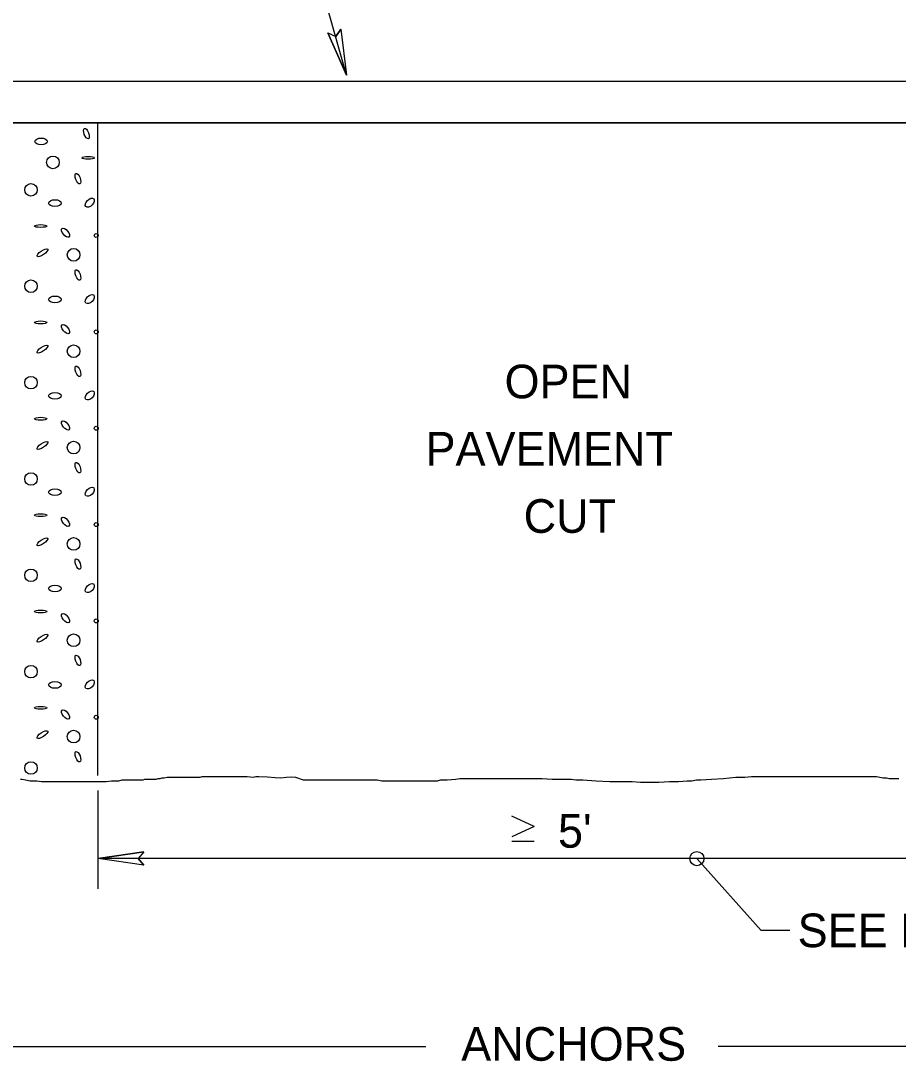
# Model space of a CAD drawing. Extents: x 12.5 to 19.6, y 6 to 16.
# Drawn here: x 14.897 to 16.462, y 11.205 to 13.061 of the extents above; entities that cross this region are included whole.
import ezdxf

# ---------------------------------------------------------------- set-up
doc = ezdxf.new("R2010")
doc.units = 0
for name, color, linetype in [('DETL-DIMS', 7, 'Continuous'), ('DETL-NOTE', 7, 'Continuous'), ('PVMT-FILL', 7, 'Continuous'), ('ROAD-EDGE', 7, 'Continuous'), ('SECT-SUBP_P', 7, 'Continuous')]:
    doc.layers.add(name, color=color, linetype=linetype)

msp = doc.modelspace()

# ---------------------------------------------------------------- linework, layer by layer
at = {"layer": 'DETL-DIMS'}
for p, q in [((15.4444, 13.0396), (15.4782, 12.964)), ((15.4444, 13.0396), (15.4587, 13.033)), ((15.4675, 13.0461), (15.4587, 13.033)), ((15.4675, 13.0461), (15.4782, 12.964)), ((15.1166, 11.5784), (15.0348, 11.5665)), ((16.7348, 11.5665), (15.0348, 11.5665)), ((15.1166, 11.5546), (15.0348, 11.5665)), ((15.1166, 11.5784), (15.1065, 11.5665)), ((15.1166, 11.5546), (15.1065, 11.5665)), ((16.2179, 11.4379), (16.103, 11.5664)), ((16.2687, 11.4379), (16.2179, 11.4379))]:
    msp.add_line(p, q, dxfattribs=at)
for points in [[(15.4782, 12.964), (15.3133, 13.5481), (15.5331, 13.5481)], [(17.2355, 12.5529), (17.6317, 11.2314), (16.1411, 11.2314)], [(14.5403, 12.5179), (14.1363, 11.2314), (15.6196, 11.2314)]]:
    msp.add_lwpolyline(points, dxfattribs=at)
for points in [[(15.4675, 13.0461), (15.4782, 12.964), (15.4444, 13.0396), (15.4587, 13.033)], [(15.1166, 11.5546), (15.0348, 11.5665), (15.1166, 11.5784), (15.1065, 11.5665)]]:
    msp.add_lwpolyline(points, close=True, dxfattribs=at)
msp.add_circle((16.103, 11.5664), 0.0126, dxfattribs=at)
at = {"layer": 'DETL-NOTE'}
for p, q in [((15.8126, 11.6237), (15.7726, 11.6423)), ((15.8126, 11.6237), (15.7726, 11.6051)), ((15.7726, 11.5976), (15.8126, 11.5976))]:
    msp.add_line(p, q, dxfattribs=at)
at = {"layer": 'PVMT-FILL'}
for points in [[(15.3005, 11.7127), (15.3114, 11.712), (15.3164, 11.713), (15.3217, 11.7131), (15.3368, 11.7124), (15.3508, 11.7112), (15.361, 11.7107), (15.3708, 11.7118), (15.3806, 11.7125), (15.387, 11.7119), (15.4009, 11.7067), (15.4179, 11.7067), (15.4433, 11.7067), (15.4602, 11.7067), (15.4747, 11.7067), (15.4892, 11.7067), (15.4953, 11.7067), (15.5062, 11.7067), (15.5207, 11.7067), (15.5328, 11.7067), (15.5412, 11.7055), (15.5642, 11.7055), (15.5799, 11.7055), (15.5969, 11.7055), (15.6041, 11.7055), (15.6114, 11.7055), (15.6235, 11.7055), (15.632, 11.7055), (15.6356, 11.7055), (15.6404, 11.7055), (15.6453, 11.7067), (15.6574, 11.7067), (15.6731, 11.7079), (15.6803, 11.7091), (15.6852, 11.7091), (15.6912, 11.7091), (15.6985, 11.7091), (15.7118, 11.7091), (15.7166, 11.7091), (15.7251, 11.7091), (15.7396, 11.7091), (15.7469, 11.7091), (15.7638, 11.7091), (15.7735, 11.7091), (15.7844, 11.7091), (15.7916, 11.7091), (15.7965, 11.7091), (15.8001, 11.7091), (15.8049, 11.7091), (15.811, 11.7091), (15.8267, 11.7091), (15.8449, 11.7079), (15.8473, 11.7079), (15.8533, 11.7079), (15.8678, 11.7079), (15.8787, 11.7079), (15.8872, 11.7067), (15.8993, 11.7067), (15.9235, 11.7055), (15.9477, 11.7043), (15.9549, 11.7043), (15.9622, 11.7043), (15.9743, 11.7043), (15.9803, 11.7043), (15.9876, 11.7043), (16.0021, 11.7031), (16.0106, 11.7031), (16.0348, 11.7031), (16.0541, 11.7043), (16.0699, 11.7043), (16.0856, 11.7055), (16.094, 11.7055), (16.1025, 11.7067), (16.1098, 11.7067), (16.1291, 11.7079), (16.1497, 11.7091), (16.1727, 11.7115), (16.1884, 11.7115), (16.2005, 11.7127), (16.2053, 11.7127), (16.2126, 11.7127), (16.2199, 11.7127), (16.2259, 11.7127), (16.2307, 11.7127), (16.2428, 11.7127), (16.2513, 11.7127), (16.2646, 11.7127), (16.2719, 11.7127), (16.2779, 11.7127), (16.2828, 11.7127), (16.2949, 11.7127), (16.3069, 11.7127), (16.3142, 11.7127), (16.3275, 11.7127), (16.3384, 11.7127), (16.3493, 11.7127), (16.3541, 11.7127), (16.3602, 11.7127), (16.3686, 11.7127), (16.3819, 11.7127), (16.3928, 11.7127), (16.3989, 11.7127), (16.4122, 11.7127), (16.4231, 11.7127), (16.4352, 11.7103), (16.4412, 11.7103), (16.4461, 11.7091), (16.4509, 11.7091), (16.463, 11.7091)], [(14.8965, 11.7079), (14.8989, 11.7079), (14.905, 11.7067), (14.9134, 11.7055), (14.9255, 11.7055), (14.934, 11.7043), (14.9437, 11.7043), (14.9485, 11.7043), (14.9521, 11.7043), (14.957, 11.7043), (14.9618, 11.7043), (14.9667, 11.7043), (14.9727, 11.7043), (14.98, 11.7043), (14.9872, 11.7043), (14.9945, 11.7043), (15.0078, 11.7043), (15.015, 11.7043), (15.0211, 11.7043), (15.0235, 11.7043), (15.0259, 11.7043), (15.0283, 11.7043), (15.0344, 11.7043), (15.0441, 11.7043), (15.0489, 11.7043), (15.0586, 11.7055), (15.0634, 11.7055), (15.0671, 11.7055), (15.0683, 11.7055), (15.0695, 11.7055), (15.0707, 11.7055), (15.0719, 11.7055), (15.0779, 11.7067), (15.0804, 11.7067), (15.084, 11.7067), (15.0864, 11.7067), (15.09, 11.7067), (15.0912, 11.7067), (15.0925, 11.7067), (15.0937, 11.7067), (15.0949, 11.7067), (15.0973, 11.7067), (15.0985, 11.7067), (15.1009, 11.7067), (15.1021, 11.7067), (15.1046, 11.7067), (15.107, 11.7067), (15.1094, 11.7067), (15.1118, 11.7067), (15.113, 11.7067), (15.1154, 11.7067), (15.1179, 11.7079), (15.1263, 11.7079), (15.1287, 11.7079), (15.1324, 11.7079), (15.1372, 11.7079), (15.1384, 11.7079), (15.1421, 11.7091), (15.1457, 11.7091), (15.1493, 11.7103), (15.1529, 11.7103), (15.1578, 11.7115), (15.1675, 11.7115), (15.1771, 11.7115), (15.182, 11.7115), (15.1868, 11.7115), (15.1929, 11.7115), (15.1965, 11.7115), (15.2025, 11.7115), (15.211, 11.7115), (15.2171, 11.7115), (15.2207, 11.7127), (15.2267, 11.7127), (15.2316, 11.7127), (15.2376, 11.7127), (15.2388, 11.7127), (15.2412, 11.7127), (15.2461, 11.7127), (15.2509, 11.7127), (15.2606, 11.7127), (15.2666, 11.7127), (15.2703, 11.7127), (15.2727, 11.7127), (15.2739, 11.7127), (15.2775, 11.7127), (15.2787, 11.7127), (15.28, 11.7127), (15.2836, 11.7127), (15.2884, 11.7127), (15.2908, 11.7127), (15.2933, 11.7127), (15.2957, 11.7127), (15.2969, 11.7127), (15.2981, 11.7127), (15.2993, 11.7127), (15.3005, 11.7127)]]:
    msp.add_lwpolyline(points, dxfattribs=at)
for centre, radius in [((14.9542, 12.8086), 0.0112), ((14.915, 12.7596), 0.0112), ((15.0314, 12.6782), 0.00349), ((14.991, 12.6437), 0.0113), ((14.915, 12.5877), 0.0112), ((15.0314, 12.5062), 0.00349), ((14.991, 12.4718), 0.0113), ((14.915, 12.4157), 0.0112), ((15.0314, 12.3343), 0.00349), ((14.991, 12.2999), 0.0113), ((14.915, 12.2438), 0.0112), ((15.0314, 12.1624), 0.00349), ((14.991, 12.1279), 0.0113), ((14.915, 12.0719), 0.0112), ((15.0314, 11.9905), 0.00349), ((14.991, 11.956), 0.0113), ((14.915, 11.9), 0.0112), ((15.0314, 11.8186), 0.00349), ((14.991, 11.7841), 0.0113), ((14.915, 11.7281), 0.0112)]:
    msp.add_circle(centre, radius, dxfattribs=at)
for centre, major_axis, ratio in [((15.0139, 12.8601), (0.00349, -0.00926), 0.407015), ((14.9332, 12.846), (0.0112, 0), 0.539468), ((15.017, 12.8167), (0.0112, 0), 0.226521), ((14.9988, 12.7796), (0.00349, -0.00926), 0.407015), ((14.9578, 12.736), (0.0112, 0), 0.539468), ((15.02, 12.7367), (-0.007, -0.007), 0.581564), ((14.9323, 12.6951), (0.0112, 0), 0.226521), ((14.9766, 12.6832), (-0.00613, 0.00777), 0.467307), ((14.9355, 12.6473), (0.00937, 0.00627), 0.338582), ((14.9988, 12.6077), (0.00349, -0.00926), 0.407015), ((14.9578, 12.5641), (0.0112, 0), 0.539468), ((15.02, 12.5647), (-0.007, -0.007), 0.581564), ((14.9323, 12.5232), (0.0112, 0), 0.226521), ((14.9766, 12.5112), (-0.00613, 0.00777), 0.467307), ((14.9355, 12.4754), (0.00937, 0.00627), 0.338582), ((14.9988, 12.4358), (0.00349, -0.00926), 0.407015), ((15.02, 12.3928), (-0.007, -0.007), 0.581564), ((14.9578, 12.3922), (0.0112, 0), 0.539468), ((14.9323, 12.3513), (0.0112, 0), 0.226521), ((14.9766, 12.3393), (-0.00613, 0.00777), 0.467307), ((14.9355, 12.3035), (0.00937, 0.00627), 0.338582), ((14.9988, 12.2639), (0.00349, -0.00926), 0.407015), ((14.9578, 12.2202), (0.0112, 0), 0.539468), ((15.02, 12.2209), (-0.007, -0.007), 0.581564), ((14.9323, 12.1793), (0.0112, 0), 0.226521), ((14.9766, 12.1674), (-0.00613, 0.00777), 0.467307), ((14.9355, 12.1316), (0.00937, 0.00627), 0.338582), ((14.9988, 12.0919), (0.00349, -0.00926), 0.407015), ((14.9578, 12.0483), (0.0112, 0), 0.539468), ((15.02, 12.049), (-0.007, -0.007), 0.581564), ((14.9323, 12.0074), (0.0112, 0), 0.226521), ((14.9766, 11.9955), (-0.00613, 0.00777), 0.467307), ((14.9355, 11.9597), (0.00937, 0.00627), 0.338582), ((14.9988, 11.92), (0.00349, -0.00926), 0.407015), ((14.9578, 11.8764), (0.0112, 0), 0.539468), ((15.02, 11.8771), (-0.007, -0.007), 0.581564), ((14.9323, 11.8355), (0.0112, 0), 0.226521), ((14.9766, 11.8236), (-0.00613, 0.00777), 0.467307), ((14.9355, 11.7877), (0.00937, 0.00627), 0.338582), ((14.9988, 11.7481), (0.00349, -0.00926), 0.407015)]:
    msp.add_ellipse(centre, major_axis=major_axis, ratio=ratio, dxfattribs=at)
at = {"layer": 'ROAD-EDGE'}
for p, q in [((13.3339, 12.8792), (18.4339, 12.8792)), ((15.0339, 12.8792), (15.0339, 11.7146)), ((15.0346, 11.6881), (15.0346, 11.5126))]:
    msp.add_line(p, q, dxfattribs=at)
at = {"layer": 'SECT-SUBP_P'}
msp.add_lwpolyline([(14.6089, 12.9536), (17.1589, 12.9536), (17.1589, 12.8792), (14.6089, 12.8792)], close=True, dxfattribs=at)

# ---------------------------------------------------------------- texts
at = {"layer": 'DETL-NOTE'}
for s, p in [('OPEN', (15.7599, 12.3877)), ('PAVEMENT', (15.6189, 12.2677)), ('CUT', (15.7939, 12.1477)), ("5'", (15.8552, 11.5859)), ('SEE NOTE #3', (16.2827, 11.4084)), ('ANCHORS', (15.6826, 11.2058))]:
    msp.add_text(s, height=0.06, dxfattribs=at).set_placement(p)

doc.saveas('drawing.dxf')
